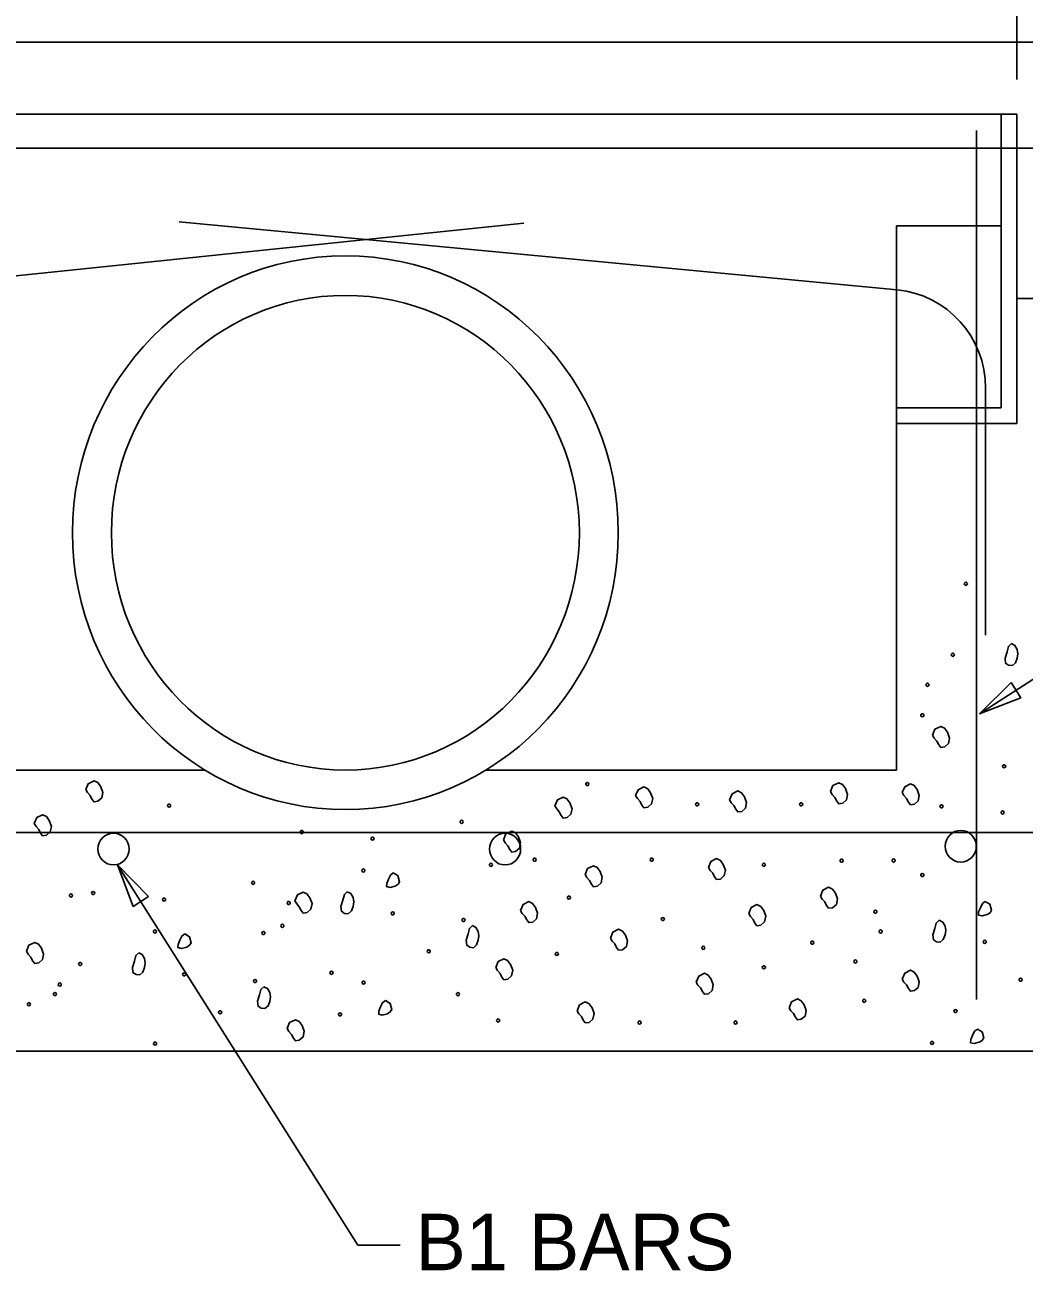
# Model space of a CAD drawing. Extents: x -439.2 to -407.9, y -458.1 to -436.2.
# Drawn here: x -412.38 to -409.689, y -445.18 to -441.825 of the extents above; entities that cross this region are included whole.
import ezdxf

# ---------------------------------------------------------------- set-up
doc = ezdxf.new("R2010")
doc.units = 0
doc.layers.add('Level 4', color=7, linetype='Continuous')

msp = doc.modelspace()

# ---------------------------------------------------------------- linework, layer by layer
at = {"layer": 'Level 4'}
for p, q in [((-409.7093, -441.9721), (-409.7093, -441.3025)), ((-413.7894, -441.872), (-409.204, -441.872)), ((-413.3253, -442.0658), (-409.7091, -442.0658)), ((-409.7511, -442.0658), (-409.7511, -442.856)), ((-409.7091, -442.0658), (-409.7091, -442.8986)), ((-409.8172, -442.1094), (-409.8172, -444.4492)), ((-413.7001, -442.1574), (-409.2933, -442.1574)), ((-411.0363, -442.3587), (-413.0244, -442.5652)), ((-411.9645, -442.3555), (-410.0312, -442.5386)), ((-410.0335, -442.3661), (-410.0335, -443.8315)), ((-410.0335, -442.3661), (-409.7511, -442.3661)), ((-409.7091, -442.5621), (-409.204, -442.5621)), ((-409.7931, -442.8036), (-409.7931, -443.4684)), ((-410.0335, -442.856), (-409.7511, -442.856)), ((-410.0335, -442.8986), (-409.7091, -442.8986)), ((-409.8094, -443.6798), (-408.9924, -443.1544)), ((-412.9935, -443.8315), (-411.8957, -443.8315)), ((-411.1386, -443.8315), (-410.0335, -443.8315)), ((-413.676, -443.9998), (-409.2933, -443.9998)), ((-412.1308, -444.0863), (-411.4837, -445.111)), ((-413.7894, -444.5887), (-409.204, -444.5887)), ((-411.4837, -445.111), (-411.3696, -445.111))]:
    msp.add_line(p, q, dxfattribs=at)
for points in [[(-409.7236, -443.491), (-409.7315, -443.4985), (-409.7353, -443.5134), (-409.7406, -443.5304), (-409.7392, -443.5437), (-409.731, -443.5493), (-409.721, -443.5503), (-409.7126, -443.5428), (-409.708, -443.5305), (-409.7062, -443.5186), (-409.708, -443.5068), (-409.714, -443.4958), (-409.7236, -443.491)], [(-409.7242, -443.596), (-409.8094, -443.6798), (-409.6984, -443.6373)], [(-409.936, -443.7377), (-409.9295, -443.7217), (-409.914, -443.714), (-409.9037, -443.7189), (-409.8958, -443.7298), (-409.8901, -443.7453), (-409.8932, -443.7601), (-409.9032, -443.769), (-409.914, -443.7706), (-409.9194, -443.7634), (-409.9243, -443.7535), (-409.9314, -443.7458), (-409.936, -443.7377)], [(-412.2163, -443.8842), (-412.2097, -443.8682), (-412.1942, -443.8605), (-412.1839, -443.8654), (-412.176, -443.8763), (-412.1703, -443.8918), (-412.1734, -443.9066), (-412.1835, -443.9155), (-412.1942, -443.9171), (-412.1997, -443.9099), (-412.2046, -443.9), (-412.2116, -443.8923), (-412.2163, -443.8842)], [(-410.7355, -443.9004), (-410.7289, -443.8844), (-410.7134, -443.8767), (-410.7031, -443.8816), (-410.6952, -443.8925), (-410.6895, -443.908), (-410.6926, -443.9228), (-410.7027, -443.9317), (-410.7134, -443.9333), (-410.7189, -443.9261), (-410.7238, -443.9162), (-410.7308, -443.9085), (-410.7355, -443.9004)], [(-410.4826, -443.9114), (-410.476, -443.8955), (-410.4605, -443.8877), (-410.4502, -443.8927), (-410.4423, -443.9035), (-410.4367, -443.919), (-410.4398, -443.9338), (-410.4498, -443.9428), (-410.4605, -443.9443), (-410.466, -443.9372), (-410.4709, -443.9272), (-410.4779, -443.9195), (-410.4826, -443.9114)], [(-410.2107, -443.8894), (-410.2041, -443.8734), (-410.1886, -443.8657), (-410.1783, -443.8706), (-410.1704, -443.8815), (-410.1647, -443.8969), (-410.1678, -443.9117), (-410.1779, -443.9207), (-410.1886, -443.9223), (-410.1941, -443.9151), (-410.199, -443.9052), (-410.206, -443.8975), (-410.2107, -443.8894)], [(-410.0176, -443.8921), (-410.011, -443.8762), (-409.9955, -443.8684), (-409.9852, -443.8733), (-409.9774, -443.8842), (-409.9717, -443.8997), (-409.9748, -443.9145), (-409.9848, -443.9235), (-409.9955, -443.925), (-410.001, -443.9179), (-410.0059, -443.9079), (-410.0129, -443.9002), (-410.0176, -443.8921)], [(-410.9528, -443.928), (-410.9463, -443.912), (-410.9308, -443.9043), (-410.9205, -443.9092), (-410.9126, -443.9201), (-410.9069, -443.9356), (-410.91, -443.9504), (-410.9201, -443.9593), (-410.9308, -443.9609), (-410.9362, -443.9538), (-410.9412, -443.9438), (-410.9482, -443.9361), (-410.9528, -443.928)], [(-412.3549, -443.9755), (-412.3483, -443.9595), (-412.3328, -443.9518), (-412.3225, -443.9567), (-412.3147, -443.9676), (-412.309, -443.9831), (-412.3121, -443.9979), (-412.3221, -444.0068), (-412.3328, -444.0084), (-412.3383, -444.0012), (-412.3432, -443.9913), (-412.3502, -443.9836), (-412.3549, -443.9755)], [(-411.0914, -444.0193), (-411.0849, -444.0033), (-411.0694, -443.9956), (-411.0591, -444.0005), (-411.0512, -444.0114), (-411.0455, -444.0269), (-411.0486, -444.0417), (-411.0587, -444.0506), (-411.0694, -444.0522), (-411.0748, -444.045), (-411.0798, -444.0351), (-411.0868, -444.0274), (-411.0914, -444.0193)], [(-412.0478, -444.1723), (-412.1308, -444.0863), (-412.0885, -444.1987)], [(-410.8714, -444.1128), (-410.8649, -444.0968), (-410.8494, -444.0891), (-410.8391, -444.094), (-410.8312, -444.1049), (-410.8255, -444.1203), (-410.8286, -444.1351), (-410.8386, -444.1441), (-410.8494, -444.1457), (-410.8548, -444.1385), (-410.8598, -444.1286), (-410.8668, -444.1209), (-410.8714, -444.1128)], [(-410.5397, -444.0935), (-410.5331, -444.0775), (-410.5176, -444.0698), (-410.5073, -444.0747), (-410.4995, -444.0856), (-410.4938, -444.101), (-410.4969, -444.1158), (-410.5069, -444.1248), (-410.5176, -444.1264), (-410.5231, -444.1192), (-410.528, -444.1093), (-410.535, -444.1016), (-410.5397, -444.0935)], [(-411.3883, -444.1083), (-411.3961, -444.1143), (-411.4013, -444.1254), (-411.406, -444.1368), (-411.4064, -444.1452), (-411.397, -444.1475), (-411.3831, -444.1438), (-411.3753, -444.139), (-411.3714, -444.132), (-411.3756, -444.1158), (-411.3883, -444.1083)], [(-411.653, -444.1836), (-411.6464, -444.1676), (-411.6309, -444.1599), (-411.6206, -444.1648), (-411.6127, -444.1757), (-411.607, -444.1912), (-411.6101, -444.206), (-411.6202, -444.2149), (-411.6309, -444.2165), (-411.6364, -444.2093), (-411.6413, -444.1994), (-411.6483, -444.1917), (-411.653, -444.1836)], [(-411.5121, -444.1591), (-411.52, -444.1667), (-411.5238, -444.1815), (-411.5291, -444.1985), (-411.5277, -444.2118), (-411.5195, -444.2175), (-411.5095, -444.2184), (-411.5011, -444.2109), (-411.4965, -444.1986), (-411.4947, -444.1867), (-411.4965, -444.1749), (-411.5025, -444.1639), (-411.5121, -444.1591)], [(-410.2379, -444.1707), (-410.2313, -444.1547), (-410.2158, -444.147), (-410.2055, -444.1519), (-410.1976, -444.1628), (-410.1919, -444.1783), (-410.195, -444.1931), (-410.2051, -444.202), (-410.2158, -444.2036), (-410.2213, -444.1964), (-410.2262, -444.1865), (-410.2332, -444.1788), (-410.2379, -444.1707)], [(-411.0455, -444.2093), (-411.0389, -444.1933), (-411.0234, -444.1856), (-411.0131, -444.1905), (-411.0052, -444.2014), (-410.9995, -444.2169), (-411.0026, -444.2317), (-411.0127, -444.2406), (-411.0234, -444.2422), (-411.0289, -444.235), (-411.0338, -444.2251), (-411.0408, -444.2174), (-411.0455, -444.2093)], [(-409.7941, -444.185), (-409.8019, -444.1909), (-409.8071, -444.2021), (-409.8119, -444.2135), (-409.8123, -444.2218), (-409.8028, -444.2242), (-409.789, -444.2205), (-409.7812, -444.2157), (-409.7773, -444.2087), (-409.7815, -444.1925), (-409.7941, -444.185)], [(-410.4309, -444.2176), (-410.4244, -444.2016), (-410.4089, -444.1939), (-410.3986, -444.1988), (-410.3907, -444.2097), (-410.385, -444.2251), (-410.3881, -444.2399), (-410.3981, -444.2489), (-410.4089, -444.2505), (-410.4143, -444.2433), (-410.4192, -444.2334), (-410.4263, -444.2257), (-410.4309, -444.2176)], [(-411.1751, -444.2504), (-411.183, -444.2579), (-411.1867, -444.2728), (-411.192, -444.2898), (-411.1906, -444.3031), (-411.1824, -444.3087), (-411.1725, -444.3097), (-411.164, -444.3022), (-411.1595, -444.2899), (-411.1577, -444.278), (-411.1595, -444.2662), (-411.1655, -444.2552), (-411.1751, -444.2504)], [(-410.8035, -444.2838), (-410.7969, -444.2678), (-410.7814, -444.2601), (-410.7711, -444.265), (-410.7632, -444.2759), (-410.7575, -444.2913), (-410.7606, -444.3061), (-410.7707, -444.3151), (-410.7814, -444.3167), (-410.7868, -444.3095), (-410.7918, -444.2996), (-410.7988, -444.2919), (-410.8035, -444.2838)], [(-409.918, -444.2358), (-409.9259, -444.2433), (-409.9297, -444.2582), (-409.935, -444.2752), (-409.9336, -444.2884), (-409.9254, -444.2941), (-409.9154, -444.295), (-409.907, -444.2875), (-409.9024, -444.2753), (-409.9006, -444.2634), (-409.9024, -444.2516), (-409.9084, -444.2406), (-409.918, -444.2358)], [(-411.9498, -444.2726), (-411.9576, -444.2786), (-411.9628, -444.2897), (-411.9675, -444.3011), (-411.968, -444.3095), (-411.9585, -444.3118), (-411.9446, -444.3081), (-411.9368, -444.3033), (-411.9329, -444.2963), (-411.9372, -444.2801), (-411.9498, -444.2726)], [(-412.376, -444.3193), (-412.3694, -444.3033), (-412.3539, -444.2956), (-412.3436, -444.3005), (-412.3357, -444.3114), (-412.33, -444.3269), (-412.3331, -444.3417), (-412.3432, -444.3506), (-412.3539, -444.3522), (-412.3594, -444.345), (-412.3643, -444.3351), (-412.3713, -444.3274), (-412.376, -444.3193)], [(-412.0736, -444.3234), (-412.0816, -444.331), (-412.0853, -444.3458), (-412.0906, -444.3628), (-412.0892, -444.3761), (-412.081, -444.3818), (-412.071, -444.3827), (-412.0626, -444.3752), (-412.0581, -444.3629), (-412.0562, -444.351), (-412.0581, -444.3392), (-412.0641, -444.3282), (-412.0736, -444.3234)], [(-411.1125, -444.3631), (-411.1059, -444.3471), (-411.0904, -444.3394), (-411.0802, -444.3443), (-411.0723, -444.3552), (-411.0666, -444.3707), (-411.0697, -444.3855), (-411.0797, -444.3944), (-411.0904, -444.396), (-411.0959, -444.3888), (-411.1008, -444.3789), (-411.1078, -444.3712), (-411.1125, -444.3631)], [(-410.5723, -444.4023), (-410.5658, -444.3864), (-410.5503, -444.3787), (-410.54, -444.3836), (-410.5321, -444.3944), (-410.5264, -444.4099), (-410.5295, -444.4247), (-410.5395, -444.4337), (-410.5503, -444.4353), (-410.5557, -444.4281), (-410.5606, -444.4181), (-410.5677, -444.4105), (-410.5723, -444.4023)], [(-410.0176, -444.3941), (-410.011, -444.3781), (-409.9955, -444.3704), (-409.9852, -444.3753), (-409.9774, -444.3862), (-409.9717, -444.4017), (-409.9748, -444.4165), (-409.9848, -444.4254), (-409.9955, -444.427), (-410.001, -444.4198), (-410.0059, -444.4099), (-410.0129, -444.4022), (-410.0176, -444.3941)], [(-411.7366, -444.4147), (-411.7445, -444.4222), (-411.7483, -444.4371), (-411.7536, -444.4541), (-411.7522, -444.4674), (-411.744, -444.473), (-411.734, -444.4739), (-411.7256, -444.4665), (-411.721, -444.4542), (-411.7192, -444.4423), (-411.721, -444.4305), (-411.727, -444.4195), (-411.7366, -444.4147)], [(-411.4093, -444.4521), (-411.4171, -444.4581), (-411.4223, -444.4692), (-411.4271, -444.4806), (-411.4275, -444.4889), (-411.418, -444.4913), (-411.4041, -444.4876), (-411.3964, -444.4828), (-411.3925, -444.4758), (-411.3967, -444.4596), (-411.4093, -444.4521)], [(-410.8932, -444.4796), (-410.8866, -444.4636), (-410.8711, -444.4559), (-410.8608, -444.4608), (-410.8529, -444.4717), (-410.8473, -444.4872), (-410.8504, -444.502), (-410.8604, -444.5109), (-410.8711, -444.5125), (-410.8766, -444.5053), (-410.8815, -444.4954), (-410.8885, -444.4877), (-410.8932, -444.4796)], [(-410.3222, -444.4713), (-410.3156, -444.4553), (-410.3001, -444.4476), (-410.2898, -444.4525), (-410.2819, -444.4634), (-410.2762, -444.4789), (-410.2793, -444.4937), (-410.2894, -444.5026), (-410.3001, -444.5042), (-410.3055, -444.4971), (-410.3105, -444.4871), (-410.3175, -444.4794), (-410.3222, -444.4713)], [(-411.674, -444.5274), (-411.6675, -444.5114), (-411.652, -444.5037), (-411.6417, -444.5086), (-411.6338, -444.5195), (-411.6281, -444.5349), (-411.6312, -444.5498), (-411.6413, -444.5587), (-411.652, -444.5603), (-411.6574, -444.5531), (-411.6624, -444.5432), (-411.6694, -444.5355), (-411.674, -444.5274)], [(-409.8152, -444.5288), (-409.823, -444.5347), (-409.8282, -444.5459), (-409.833, -444.5573), (-409.8334, -444.5656), (-409.8239, -444.568), (-409.81, -444.5643), (-409.8023, -444.5595), (-409.7983, -444.5525), (-409.8026, -444.5363), (-409.8152, -444.5288)]]:
    msp.add_lwpolyline(points, close=True, dxfattribs=at)
for centre, major_axis in [((-411.5172, -443.1925), (0, 0.7455)), ((-411.5172, -443.1925), (0, 0.639)), ((-412.1415, -444.0443), (0, 0.0426)), ((-411.0872, -444.0443), (0, 0.0426)), ((-409.8601, -444.0365), (0, 0.0426))]:
    msp.add_ellipse(centre, major_axis=major_axis, ratio=0.985935, dxfattribs=at)
for centre, major_axis, start_param, end_param in [((-410.0556, -442.8036), (0, 0.2662), 4.712389, 6.190084), ((-409.8463, -443.3301), (0, 0.00422), 4.712389, 7.853982), ((-409.8463, -443.3301), (0, 0.00422), 1.570796, 4.712389), ((-409.8813, -443.5213), (0, 0.00422), 4.712389, 7.853982), ((-409.8813, -443.5213), (0, 0.00422), 1.570796, 4.712389), ((-409.9495, -443.6021), (0, 0.00422), 4.712389, 7.853982), ((-409.9495, -443.6021), (0, 0.00422), 1.570796, 4.712389), ((-409.9635, -443.6839), (0, 0.00422), 4.712389, 7.853982), ((-409.9635, -443.6839), (0, 0.00422), 1.570796, 4.712389), ((-409.7431, -443.8213), (0, 0.00422), 4.712389, 7.853982), ((-409.7431, -443.8213), (0, 0.00422), 1.570796, 4.712389), ((-410.8657, -443.8691), (0, 0.00422), 4.712389, 7.853982), ((-410.8657, -443.8691), (0, 0.00422), 1.570796, 4.712389), ((-411.992, -443.9271), (0, 0.00422), 4.712389, 7.853982), ((-410.5699, -443.9238), (0, 0.00422), 4.712389, 7.853982), ((-410.5699, -443.9238), (0, 0.00422), 1.570796, 4.712389), ((-410.2898, -443.9238), (0, 0.00422), 4.712389, 7.853982), ((-410.2898, -443.9238), (0, 0.00422), 1.570796, 4.712389), ((-411.992, -443.9271), (0, 0.00422), 1.570796, 4.712389), ((-409.9118, -443.9294), (0, 0.00422), 4.712389, 7.853982), ((-409.9118, -443.9294), (0, 0.00422), 1.570796, 4.712389), ((-409.7472, -443.9457), (0, 0.00422), 4.712389, 7.853982), ((-409.7472, -443.9457), (0, 0.00422), 1.570796, 4.712389), ((-411.2042, -443.9709), (0, 0.00422), 4.712389, 7.853982), ((-411.2042, -443.9709), (0, 0.00422), 1.570796, 4.712389), ((-411.6348, -443.9983), (0, 0.00422), 4.712389, 7.853982), ((-411.6348, -443.9983), (0, 0.00422), 1.570796, 4.712389), ((-411.4441, -444.0161), (0, 0.00422), 4.712389, 7.853982), ((-411.4441, -444.0161), (0, 0.00422), 1.570796, 4.712389), ((-411.1253, -444.0866), (0, 0.00422), 4.712389, 7.853982), ((-411.1253, -444.0866), (0, 0.00422), 1.570796, 4.712389), ((-411.0077, -444.0728), (0, 0.00422), 4.712389, 7.853982), ((-411.0077, -444.0728), (0, 0.00422), 1.570796, 4.712389), ((-410.6922, -444.0728), (0, 0.00422), 4.712389, 7.853982), ((-410.6922, -444.0728), (0, 0.00422), 1.570796, 4.712389), ((-410.3904, -444.0866), (0, 0.00422), 4.712389, 7.853982), ((-410.3904, -444.0866), (0, 0.00422), 1.570796, 4.712389), ((-410.181, -444.0755), (0, 0.00422), 4.712389, 7.853982), ((-410.181, -444.0755), (0, 0.00422), 1.570796, 4.712389), ((-410.0407, -444.0749), (0, 0.00422), 4.712389, 7.853982), ((-410.0407, -444.0749), (0, 0.00422), 1.570796, 4.712389), ((-411.4687, -444.1018), (0, 0.00422), 4.712389, 7.853982), ((-411.4687, -444.1018), (0, 0.00422), 1.570796, 4.712389), ((-409.9635, -444.1141), (0, 0.00422), 4.712389, 7.853982), ((-409.9635, -444.1141), (0, 0.00422), 1.570796, 4.712389), ((-412.1964, -444.1626), (0, 0.00422), 4.712389, 7.853982), ((-411.7657, -444.1352), (0, 0.00422), 4.712389, 7.853982), ((-411.7657, -444.1352), (0, 0.00422), 1.570796, 4.712389), ((-412.2564, -444.1692), (0, 0.00422), 4.712389, 7.853982), ((-412.2564, -444.1692), (0, 0.00422), 1.570796, 4.712389), ((-412.1964, -444.1626), (0, 0.00422), 1.570796, 4.712389), ((-412.0056, -444.1803), (0, 0.00422), 4.712389, 7.853982), ((-412.0056, -444.1803), (0, 0.00422), 1.570796, 4.712389), ((-411.6698, -444.1894), (0, 0.00422), 4.712389, 7.853982), ((-411.6698, -444.1894), (0, 0.00422), 1.570796, 4.712389), ((-410.9152, -444.1748), (0, 0.00422), 4.712389, 7.853982), ((-410.9152, -444.1748), (0, 0.00422), 1.570796, 4.712389), ((-411.3897, -444.2174), (0, 0.00422), 4.712389, 7.853982), ((-411.3897, -444.2174), (0, 0.00422), 1.570796, 4.712389), ((-410.09, -444.213), (0, 0.00422), 4.712389, 7.853982), ((-410.09, -444.213), (0, 0.00422), 1.570796, 4.712389), ((-411.6868, -444.2509), (0, 0.00422), 4.712389, 7.853982), ((-411.6868, -444.2509), (0, 0.00422), 1.570796, 4.712389), ((-411.199, -444.2352), (0, 0.00422), 4.712389, 7.853982), ((-411.199, -444.2352), (0, 0.00422), 1.570796, 4.712389), ((-410.6623, -444.2327), (0, 0.00422), 4.712389, 7.853982), ((-410.6623, -444.2327), (0, 0.00422), 1.570796, 4.712389), ((-412.0302, -444.2661), (0, 0.00422), 4.712389, 7.853982), ((-412.0302, -444.2661), (0, 0.00422), 1.570796, 4.712389), ((-411.738, -444.2703), (0, 0.00422), 4.712389, 7.853982), ((-411.738, -444.2703), (0, 0.00422), 1.570796, 4.712389), ((-410.2599, -444.2962), (0, 0.00422), 4.712389, 7.853982), ((-410.0757, -444.2661), (0, 0.00422), 4.712389, 7.853982), ((-410.0757, -444.2661), (0, 0.00422), 1.570796, 4.712389), ((-409.7956, -444.2941), (0, 0.00422), 4.712389, 7.853982), ((-409.7956, -444.2941), (0, 0.00422), 1.570796, 4.712389), ((-411.2929, -444.3193), (0, 0.00422), 4.712389, 7.853982), ((-411.2929, -444.3193), (0, 0.00422), 1.570796, 4.712389), ((-410.9478, -444.3265), (0, 0.00422), 4.712389, 7.853982), ((-410.9478, -444.3265), (0, 0.00422), 1.570796, 4.712389), ((-410.5535, -444.31), (0, 0.00422), 4.712389, 7.853982), ((-410.5535, -444.31), (0, 0.00422), 1.570796, 4.712389), ((-410.2599, -444.2962), (0, 0.00422), 1.570796, 4.712389), ((-412.2314, -444.3537), (0, 0.00422), 4.712389, 7.853982), ((-412.2314, -444.3537), (0, 0.00422), 1.570796, 4.712389), ((-410.3904, -444.3624), (0, 0.00422), 4.712389, 7.853982), ((-410.1439, -444.3469), (0, 0.00422), 4.712389, 7.853982), ((-410.1439, -444.3469), (0, 0.00422), 1.570796, 4.712389), ((-411.9513, -444.3817), (0, 0.00422), 4.712389, 7.853982), ((-411.9513, -444.3817), (0, 0.00422), 1.570796, 4.712389), ((-411.5545, -444.3773), (0, 0.00422), 4.712389, 7.853982), ((-411.5545, -444.3773), (0, 0.00422), 1.570796, 4.712389), ((-410.3904, -444.3624), (0, 0.00422), 1.570796, 4.712389), ((-409.6988, -444.396), (0, 0.00422), 4.712389, 7.853982), ((-412.2866, -444.409), (0, 0.00422), 4.712389, 7.853982), ((-412.2866, -444.409), (0, 0.00422), 1.570796, 4.712389), ((-411.7605, -444.3995), (0, 0.00422), 4.712389, 7.853982), ((-411.7605, -444.3995), (0, 0.00422), 1.570796, 4.712389), ((-411.4683, -444.4037), (0, 0.00422), 4.712389, 7.853982), ((-411.4683, -444.4037), (0, 0.00422), 1.570796, 4.712389), ((-409.6988, -444.396), (0, 0.00422), 1.570796, 4.712389), ((-412.3693, -444.462), (0, 0.00422), 4.712389, 7.853982), ((-412.2995, -444.4345), (0, 0.00422), 4.712389, 7.853982), ((-412.2995, -444.4345), (0, 0.00422), 1.570796, 4.712389), ((-411.214, -444.435), (0, 0.00422), 4.712389, 7.853982), ((-411.214, -444.435), (0, 0.00422), 1.570796, 4.712389), ((-410.1202, -444.4528), (0, 0.00422), 4.712389, 7.853982), ((-410.1202, -444.4528), (0, 0.00422), 1.570796, 4.712389), ((-412.3693, -444.462), (0, 0.00422), 1.570796, 4.712389), ((-411.8544, -444.4836), (0, 0.00422), 4.712389, 7.853982), ((-411.8544, -444.4836), (0, 0.00422), 1.570796, 4.712389), ((-411.5316, -444.4894), (0, 0.00422), 4.712389, 7.853982), ((-411.5316, -444.4894), (0, 0.00422), 1.570796, 4.712389), ((-409.8741, -444.4804), (0, 0.00422), 4.712389, 7.853982), ((-409.8741, -444.4804), (0, 0.00422), 1.570796, 4.712389), ((-411.1058, -444.5058), (0, 0.00422), 4.712389, 7.853982), ((-411.1058, -444.5058), (0, 0.00422), 1.570796, 4.712389), ((-410.7249, -444.5113), (0, 0.00422), 4.712389, 7.853982), ((-410.7249, -444.5113), (0, 0.00422), 1.570796, 4.712389), ((-410.4665, -444.5113), (0, 0.00422), 4.712389, 7.853982), ((-410.4665, -444.5113), (0, 0.00422), 1.570796, 4.712389), ((-409.9374, -444.5661), (0, 0.00422), 4.712389, 7.853982), ((-412.0298, -444.568), (0, 0.00422), 4.712389, 7.853982), ((-412.0298, -444.568), (0, 0.00422), 1.570796, 4.712389), ((-409.9374, -444.5661), (0, 0.00422), 1.570796, 4.712389)]:
    msp.add_ellipse(centre, major_axis=major_axis, ratio=0.985935, start_param=start_param, end_param=end_param, dxfattribs=at)

# ---------------------------------------------------------------- texts
msp.add_text('B1 BARS', height=0.15214, dxfattribs=at).set_placement((-411.3285, -445.1783))

doc.saveas('drawing.dxf')
